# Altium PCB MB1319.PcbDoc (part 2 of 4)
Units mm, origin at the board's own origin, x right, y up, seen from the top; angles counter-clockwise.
Board outline 70 x 82.5 mm, 2 copper layers (Top Layer, Bottom Layer), stack 1.571 mm thick; 252 components, 179 nets, 814 pads, 1000 vias.
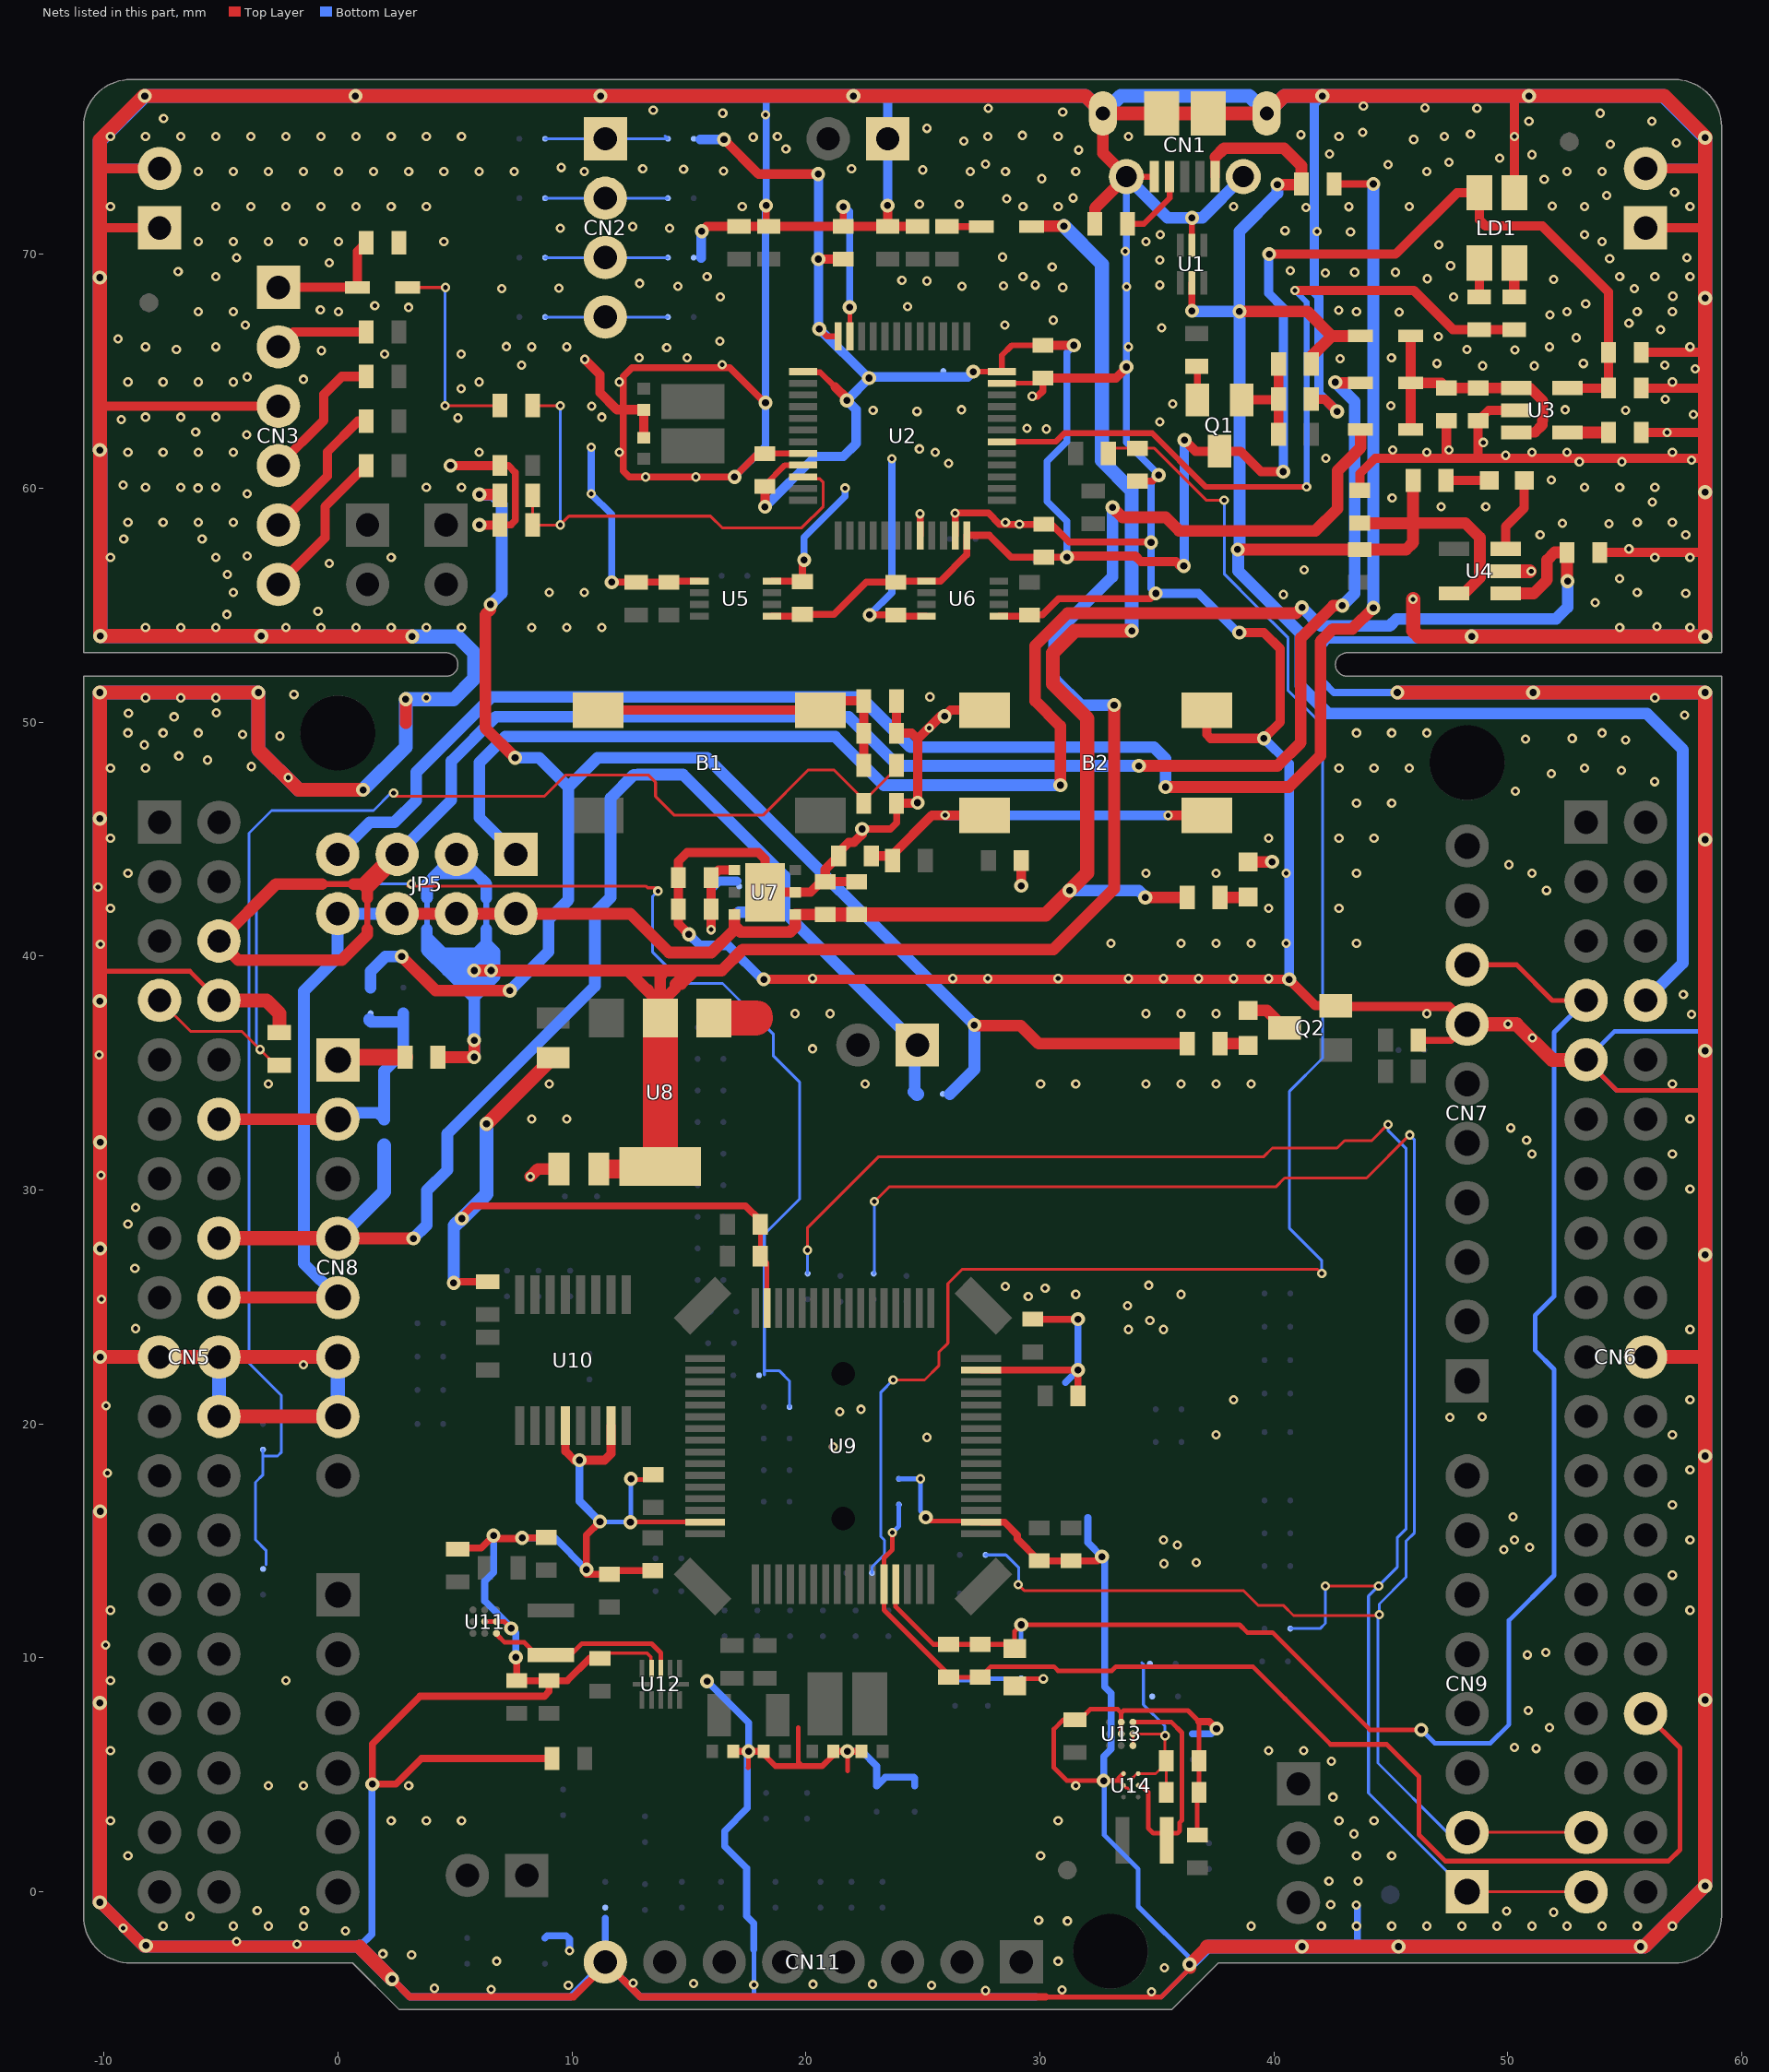
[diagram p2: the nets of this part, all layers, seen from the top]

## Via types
v1: diameter 0.4, hole 0.2, Top Layer to Bottom Layer, tented both sides, 802 vias
v2: diameter 0.6, hole 0.3, Top Layer to Bottom Layer, tented both sides, 198 vias

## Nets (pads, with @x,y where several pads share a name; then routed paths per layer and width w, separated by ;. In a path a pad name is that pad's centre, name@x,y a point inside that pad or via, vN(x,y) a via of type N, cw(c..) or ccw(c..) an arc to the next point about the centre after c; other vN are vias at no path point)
3V3: CN5.16 CN8.4 JP6.1 SB13.2 SB20.1 SB21.2 | length 61
  Top Layer w0.5: CN8.4@0,27.94 0.015,27.925 v2(3.225,27.925)
  Top Layer w0.6: CN5.16@-5.08,27.94 CN8.4@0,27.94
  Bottom Layer w0.5: v2(3.225,27.925) 3.8,28.5 3.8,29.975 4.675,30.85 4.675,32.4 10.981,38.706 10.981,41.834 11.65,42.503 ; 11.65,44.775 11.65,42.503 ; SB13.2@17.15,41.875 19.085,41.875 ; 24.65,34.2 JP6.1@24.65,36.08 ; JP6.1@24.765,36.195 19.085,41.875 ; 11.65,42.503 11.65,46.75 12.65,47.75 12.829,47.75 12.831,47.752 14.748,47.752 19.085,43.415 19.085,41.875
  Bottom Layer w0.6: CN8.4@0,27.94 1.975,29.915 SB21.2@1.975,31.9 ; 24.65,34.2 SB20.1@24.75,34.1 ; JP6.1@24.65,36.08 JP6.1@24.765,36.195
3V3_PER: R22.1 R34.1 SB15.2 SB20.2 | length 70.7
  Top Layer w0.5: v2(2.725,39.975) 4.175,38.525 v2(7.35,38.525) ; v2(6.05,59.725) 6.885,59.725 R22.1@6.92,59.69 ; v2(6.525,55.025) 6.525,54.81 6.3,54.585 6.3,49.75 v2(7.575,48.475) ; v2(27.2,37.05) 27.225,37.025 29.175,37.025 29.95,36.25 R34.1@36.3,36.25
  Bottom Layer w0.5: SB15.2@1.4,38.65 1.4,39.35 2.025,39.975 v2(2.725,39.975) ; v2(6.05,59.725) 6.025,59.7 6.625,59.7 7,59.325 7,55.5 v2(6.525,55.025) ; v2(7.35,38.525) 9,40.175 9,41.55 9.85,42.4 ; v2(7.575,48.475) 8.6,48.475 9.85,47.225 ; 9.85,43.925 9.85,42.4 ; 26.15,34.1 27.2,35.15 v2(27.2,37.05) 15.775,48.475 11.1,48.475 9.85,47.225 ; 9.85,42.4 9.85,47.225
3V3_ST_LINK: C1.2 C2.2 C3.2 C4.2 C11.2 C14.2 C16.2 C18.2 LD1.4 Q1.3 SB1.2 SB9.1 U2.1 U2.9 U2.24 U2.36 U2.48 U3.5 U5.1 U6.1 | length 114.3
  Top Layer w0.25: C11.2@18.25,60.075 18.25,60.125 19.105,60.98 U2.9@19.88,60.98 ; U2.1@19.88,64.98 19.905,64.955 20.615,64.955 21.245,64.325 ; v2(20.575,66.8) 20.895,66.48 U2.48@21.38,66.48 ; v2(27.15,64.975) 28.375,64.975 U2.36@28.38,64.98 28.38,65.68 28.8,66.1 C2.2@30.125,66.1
  Top Layer w0.3: U5.1@18.55,54.525 19.775,54.525 C16.2@19.85,54.6 21.2,54.6 22.575,55.975 C18.2@23.85,55.975 23.9,56.025 U6.1@25.15,56.025 25.75,56.025 26.88,57.155 U2.24@26.88,57.98 27.845,57.98 28.775,57.05 C14.2@30.175,57.05 v2(31.15,57.05)
  Top Layer w0.4: v2(16.5,74.9) 17.975,73.425 v2(20.525,73.425) ; v2(18.25,59.2) C11.2@18.25,60.075 ; v2(20.535,69.785) C1.2@21.59,69.785 ; 21.245,64.325 21.75,63.82 v2(21.75,63.75) ; C2.2@30.125,66.1 v2(31.45,66.1) ; v2(31.15,57.05) 31.2,57.1 34.075,57.1 34.315,56.86 35.816,56.86 36.001,56.675 v2(36.15,56.675) ; v2(36.175,62.05) 36.65,61.575 Q1.3@37.675,61.575 38.575,61.575 39.45,60.7 v2(40.4,60.7) ; v2(39.8,70) 45.2,70 47.82,72.62 LD1.4@48.78,72.62 48.78,71.47 49.05,71.2 51.475,71.2 54.3,68.375 C3.2@54.3,65.8 C4.2@54.3,64.275 U3.5@52.55,64.275
  Bottom Layer w0.3: v2(31.15,57.05) 31.15,58.575 30.3,59.425 30.3,61.15 31.15,62 31.15,65.8 v2(31.45,66.1)
  Bottom Layer w0.4: 15.475,74.9 v2(16.5,74.9) ; v2(18.25,59.2) 20.4,61.35 21.6,61.35 22.15,61.9 22.15,63.35 v2(21.75,63.75) v2(22.7,64.7) ; v2(20.525,73.425) 20.535,73.415 v2(20.535,69.785) 20.535,66.84 v2(20.575,66.8) 22.675,64.7 v2(22.7,64.7) ; v2(27.15,64.975) 26.925,64.75 22.75,64.75 v2(22.7,64.7) ; v2(36.15,56.675) 36.175,56.7 v2(36.175,62.05) ; v2(39.8,70) 39.775,69.975 39.775,68.325 40.4,67.7 v2(40.4,60.7)
5V: C25.2 C26.2 CN5.18 CN8.5 D1.1 JP5.2 JP5.4 JP5.6 JP5.8 R29.2 U7.1 U7.6 | length 97.1
  Top Layer w0.5: JP5.6@2.53,41.805 JP5.4@5.07,41.805 JP5.2@7.61,41.805 JP5.2@8.08,41.805 ; JP5.2@8.08,41.52 JP5.2@8.08,41.805 ; U7.6@16.95,41.775 16.95,41.289 ; C25.2@20.825,41.775 U7.1@19.55,41.775 19.55,41.25 19.325,41.025 17.214,41.025 16.95,41.289 ; D1.1@29.645,71.175 29.67,71.2 v2(31.025,71.2) ; v2(34.5,42.5) R29.2@36.3,42.5 R29.2@36.325,42.475 ; JP5.2@8.08,41.805 12.495,41.805 14.154,40.146 15.961,40.146 16.95,41.135 16.95,41.289
  Top Layer w0.508: CN5.18@-5.08,25.4 CN8.5@0,25.4
  Top Layer w0.6: C25.2@20.825,41.775 C26.2@22.175,41.775 30.25,41.775 v2(31.275,42.8) 32.025,43.55 32.025,50.15 30.55,51.625 30.55,52.957 31.493,53.9 v2(33.925,53.9)
  Bottom Layer w0.5: CN8.5@0,25.4 -1.45,26.85 -1.45,38.5 -0.01,39.94 JP5.8@-0.01,41.805 JP5.6@2.53,41.805 ; v2(31.275,42.8) 34.225,42.8 34.525,42.5 v2(34.5,42.5)
  Bottom Layer w0.6: v2(31.025,71.2) 32.65,69.575 32.65,61.175 33.925,59.9 v2(33.925,53.9)
5V_STLINK: C13.1 CN1.1 CN6.8 D3.1 R1.1 R13.1 R21.2 R25.1 U1.5 U4.5 | length 88.5
  Top Layer w0.3: v2(36.5,67.575) U1.5@36.5,68.77
  Top Layer w0.4: CN1.1@37.495,73.31 37.495,74.145 ; R1.1@41.15,72.975 R1.1@41.175,73
  Top Layer w0.5: 37.495,74.145 37.875,74.525 40.425,74.525 41.175,73.775 R1.1@41.175,73 ; v2(38.529,67.546) 41.421,67.546 41.425,67.55 42.475,66.5 ; v2(40.15,72.975) R1.1@41.15,72.975 ; 45.93,58.5 45.95,58.5 48.186,58.5 48.8,57.886 48.8,56.175 48.125,55.5 U4.5@47.7,55.5
  Top Layer w0.508: v2(38.45,57.375) R25.1@43.675,57.375 45.65,57.375 45.95,57.675 45.95,58.5 45.95,58.52 ; R13.1@41.6,65.3 41.6,65.625 42.475,66.5 D3.1@43.705,66.5 ; C13.1@43.675,58.5 45.93,58.5 45.95,58.52 ; R21.2@45.95,60.325 45.95,58.52
  Bottom Layer w0.25: v2(36.5,67.575) v2@36.525,67.55
  Bottom Layer w0.5: v2@36.525,67.55 36.529,67.546 v2(38.529,67.546) 38.529,70.679 38.529,70.979 40.15,72.6 v2(40.15,72.975)
  Bottom Layer w0.508: v2(38.529,67.546) 38.529,57.454 v2(38.45,57.375) 38.475,57.375 38.475,56.454 39.746,55.183 39.746,55.179 40.129,54.796 40.133,54.796 41.125,53.804 41.125,51.55 42.311,50.364 44.642,50.364 ; 45.075,50.364 44.642,50.364 ; CN6.8@55.88,38.1 57.475,39.695 57.475,48.825 55.936,50.364 44.642,50.364
5V_STLINK_SW: C15.2 JP5.1 U4.1 | length 68.2
  Top Layer w0.4: v2@41.15,54.9 v2(41.2,54.9)
  Top Layer w0.5: 30.875,48.025 v2(30.875,47.3) 30.875,49.825 29.8,50.9 29.8,53.268 31.182,54.65 40.95,54.65 v2(41.2,54.9) ; U4.1@49.9,55.5 51.1,55.5 51.675,56.075 51.675,56.925 52,57.25 C15.2@52.525,57.25 52.525,56.05 v2(52.55,56.025)
  Bottom Layer w0.5: JP5.1@7.61,44.345 6.05,45.905 6.05,48.275 7.15,49.375 21.25,49.375 23.325,47.3 v2(30.875,47.3) ; v2(41.2,54.9) 41.99,54.11 42.425,54.11 44.95,54.11 45.25,54.41 52.05,54.41 52.55,54.91 v2(52.55,56.025)
5V_USB_CHG: JP5.7 R1.2 | length 75.9
  Top Layer w0.3: R1.2@42.575,73 v2(44.25,73)
  Top Layer w0.5: v2(35.37,47.22) 40.645,47.22 41.99,48.565 41.99,53.438 42.527,53.975 43.35,53.975 v2(44.25,54.875)
  Bottom Layer w0.5: JP5.7@-0.01,44.345 1.355,45.71 1.95,45.71 1.96,45.72 2.42,45.72 3.35,46.65 3.35,47.862 6.563,51.075 22.325,51.075 24.475,48.925 34.875,48.925 35.37,48.43 v2(35.37,47.22) ; v2(44.25,54.875) v2(44.25,73)
5V_VIN: C29.2 D5.1 JP5.3 R35.2 U8.2 U8.4 | length 114.6
  Top Layer w0.5: R35.2@4.275,35.675 v2(5.825,35.675) v2(5.825,36.4) ; v2(5.825,39.377) 5.827,39.375 v2@5.843,39.375 ; v2@5.835,39.367 v2@5.843,39.375 ; v2(6.548,39.377) 5.845,39.377 v2@5.843,39.375 ; 13.25,38.55 13.2,38.55 ; U8.2@13.775,37.35 U8.2@13.775,37.975 ; 15.775,39.375 15.25,39.375 ; v2(33.102,59.175) 33.527,58.75 35.375,58.75 35.95,58.175 41.775,58.175 42.725,59.125 42.725,60.75 43.705,61.73 D5.1@43.705,62.5 ; 33.175,42.875 30.575,40.275 17.3,40.275 16.4,39.375 15.25,39.375 ; 33.175,42.95 v2(33.175,50.725) ; v2@5.843,39.375 12.375,39.375 ; 12.375,39.375 13.2,38.55 ; 12.375,39.375 13.775,39.375 ; 13.2,38.55 U8.2@13.775,37.975 ; U8.2@13.775,37.975 13.775,39.15 ; U8.2@13.775,37.975 14.425,38.625 14.425,38.8 ; 13.775,39.15 14,39.375 ; 13.775,39.15 13.775,39.375 ; 13.775,39.375 14,39.375 ; 14,39.375 15,39.375 ; 14.425,38.8 15,39.375 ; 14.425,38.8 14.675,38.8 15.25,39.375 ; 15,39.375 15.25,39.375
  Top Layer w0.8: C29.2@11.15,30.9 13.675,30.9 U8.4@13.775,31
  Top Layer w1.5: U8.4@13.775,31 U8.2@13.775,37.35
  Bottom Layer w0.25: 3.8,41.13 3.81,41.141 3.81,42.49 ; 6.34,41.13 6.34,42.48
  Bottom Layer w0.3: 30.675,51.8 30.675,53.775 ; v2@33,59.175 v2(33.102,59.175)
  Bottom Layer w0.5: 3.8,41.13 3.8,40.8 ; 3.81,42.49 3.81,43.085 4.25,43.525 ; v2(5.825,35.675) v2(5.825,36.4) 5.825,38.325 ; v2(5.825,39.377) 5.825,38.654 ; 6.34,41.13 6.34,40.525 ; 6.34,42.48 6.34,43.075 5.875,43.54 ; v2(33.102,59.175) 33.102,56.202 30.675,53.775 30.6,53.7 30.6,51.875 30.675,51.8 31.75,50.725 v2(33.175,50.725) ; 3.8,40.8 4.495,40.105 ; 3.8,40.8 3.8,40.25 4.673,39.377 ; 4.25,43.525 JP5.3@5.07,44.345 5.875,43.54 ; 4.25,43.525 5.86,43.525 5.875,43.54 ; 4.495,40.105 4.825,39.775 5.59,39.775 5.92,40.105 ; 4.495,40.105 5.92,40.105 ; 4.673,39.377 5.725,38.325 5.825,38.325 ; 4.673,39.377 5.102,39.377 ; 5.102,39.377 5.825,38.654 ; 5.102,39.377 v2(5.825,39.377) ; 5.825,38.325 5.825,38.654 ; 5.825,38.325 5.9,38.325 6.7,39.125 6.7,40.165 6.34,40.525 ; 5.825,38.654 v2(6.548,39.377) ; v2(5.825,39.377) 6.34,39.892 ; v2(5.825,39.377) v2(6.548,39.377) ; 5.92,40.105 6.34,40.525 ; 6.34,39.892 6.34,40.525 ; 6.34,39.892 6.34,39.585 v2(6.548,39.377)
AGND: C40.2 C41.1 CN6.32 SB56.2 U9.12 | length 52.3
  Top Layer w0.2: v1@23.773,15.279 v1(23.701,15.351) 23.701,14.63 23.34,14.269 U9.12@23.34,13.15 23.34,12.049 26.1,9.289 C41.1@26.1,9.175 ; C41.1@25.767,9.175 C41.1@26.1,9.175 ; CN6.32@55.88,7.62 57.35,6.15 57.35,1.8 56.865,1.315 47.325,1.315 46.2,2.44 46.2,4.925 44.825,6.3 42.425,6.3 40.475,8.25 39.1,9.625 33.25,9.625 33.075,9.45 30.775,9.45 30.6,9.625 27.9,9.625 C40.2@27.45,9.175 C41.1@26.1,9.175
  Bottom Layer w0.2: v1(23.701,15.351) 23.975,15.625 SB56.2@23.975,16.55
AIN_1: R16.2 R22.2 R24.2 U2.10 | length 22.7
  Top Layer w0.127: R22.2@8.32,59.69 R24.2@8.32,58.42 v1@9.5,58.42 ; R16.2@8.325,63.525 v1(9.5,63.525) ; v1(9.5,58.425) 9.876,58.801 15.924,58.801 16.423,58.302 19.824,58.302 20.744,59.221 20.744,60.239 20.589,60.393 19.967,60.393 U2.10@19.88,60.48
  Bottom Layer w0.127: v1(9.5,58.425) v1(9.5,63.525)
ARD_D0_RX: CN6.37 CN9.1 SB33.2 SB73.2 | length 74.7
  Top Layer w0.12: v1(20.075,27.425) 20.075,28.395 23.09,31.41 39.55,31.41 39.93,31.79 42.7,31.79 43.02,32.11 44.185,32.11 v1(44.875,32.8) ; v1(42.2,13.075) v1(44.475,13.075) v1@44.5,13.075 ; CN9.1@48.26,0 CN6.37@53.34,0
  Bottom Layer w0.12: SB33.2@20.075,26.425 v1(20.075,27.425) ; SB73.2@40.7,11.25 41.975,11.25 42.2,11.475 v1(42.2,13.075) ; v1(44.875,32.8) 44.875,32.55 45.64,31.785 45.64,15.502 45.27,15.132 45.27,13.87 v1(44.475,13.075) 44.042,12.642 44.042,4.218 CN9.1@48.26,0
ARD_D1_TX: CN6.35 CN9.2 SB35.2 SB60.2 | length 83.3
  Top Layer w0.12: v1(22.925,29.5) 23.555,30.13 40.08,30.13 40.46,30.51 43.96,30.51 v1(45.8,32.35) ; v1(29.076,13.126) 29.322,12.88 38.695,12.88 39.34,12.235 40.416,12.235 40.84,11.811 44.502,11.811 v1(44.502,11.851) ; CN9.2@48.26,2.54 CN6.35@53.34,2.54
  Bottom Layer w0.12: SB35.2@22.9,26.425 22.925,26.45 v1(22.925,29.5) ; SB60.2@27.675,14.4 28.55,14.4 29.1,13.85 29.1,13.149 v1(29.076,13.126) ; v1(44.502,11.851) 44.502,12.302 45.64,13.44 45.64,14.978 46.01,15.348 46.01,32.14 v1(45.8,32.35) ; v1@44.595,11.851 44.45,11.706 44.45,5.5 47.41,2.54 CN9.2@48.26,2.54
AVDD: C40.1 C41.2 CN6.7 CN7.8 L2.2 SB74.2 U9.13 | length 72.8
  Top Layer w0.2: U9.13@23.84,13.15 23.84,12.185 25.45,10.575 C41.2@26.1,10.575 C40.1@27.45,10.575 28.75,10.575 L2.2@28.925,10.4 28.925,11.138 v2(29.202,11.415) 38.534,11.415 38.864,11.085 ; 39.35,11.085 38.864,11.085 ; v2@46.35,6.925 44.1,6.925 39.94,11.085 38.864,11.085 ; CN7.8@48.26,39.624 50.376,39.624 51.9,38.1 CN6.7@53.34,38.1
  Bottom Layer w0.2: v2@29.142,11.475 v2(29.202,11.415) 29.2,11.413 SB74.2@29.2,10.225 ; v2(46.3,6.925) 46.875,6.35 49.25,6.35 50.05,7.15 50.05,11.6 51.975,13.525 51.975,22.334 51.16,23.149 51.16,24.636 51.975,25.451 ; 51.975,26.525 51.975,25.451 ; CN6.7@53.34,38.1 51.975,36.735 51.975,25.451
B_USER: C21.2 R30.1 SB50.1 SB62.1 | length 65.4
  Top Layer w0.12: v1(2.381,46.964) 2.364,46.964 2.275,46.875 2.326,46.824 8.826,46.824 9.742,47.74 13.261,47.74 13.575,47.426 13.575,46.822 14.382,46.015 18.165,46.015 20.109,47.959 21.191,47.959 22.475,46.675 C21.2@22.475,46.625 ; C21.2@22.475,46.525 C21.2@22.475,46.625 ; R30.1@23.875,48.15 23.875,48.025 C21.2@22.475,46.625
  Bottom Layer w0.12: SB50.1@-3.2,18.9 -3.2,18.625 ; -3.075,13.975 -3.075,14.6 -3.525,15.05 -3.525,17.5 -3.2,17.825 -3.2,18.625 ; v1(2.381,46.964) 2.264,46.964 1.52,46.22 -2.83,46.22 -3.8,45.25 -3.8,22.6 -2.41,21.21 -2.41,18.79 -2.575,18.625 -3.2,18.625
BOOT0: CN5.7 R32.2 SB45.2 SB48.2 | length 57.8
  Top Layer w0.12: CN5.7@-7.62,38.1 -6.295,36.775 -4.1,36.775 v1(-3.325,36) -2.65,35.325 R32.2@-2.5,35.325 ; v1(3.134,43.075) 3.07,43.075 2.985,42.99 13.159,42.99 13.234,42.915 13.535,42.915 v1(13.675,42.775)
  Bottom Layer w0.12: v1(-3.325,36) -3.48,36.155 -3.48,42.195 -2.6,43.075 v1(3.134,43.075) ; v1(13.675,42.775) 13.454,42.554 13.454,40.161 14.785,38.83 16.445,38.83 18.605,36.67 18.605,35.736 19.725,34.616 19.725,31.227 19.725,29.603 18.225,28.103 18.225,23.175
  Bottom Layer w0.127: 18.225,22.1 18.225,22.275 ; 18.225,23.175 18.225,22.275 ; SB48.2@19.3,20.725 19.3,21.825 18.85,22.275 18.225,22.275
E5V: CN5.6 D4.1 JP5.5 | length 80.2
  Top Layer w0.25: -0.685,43.075 0.665,43.075 ; 1.26,41.13 1.26,42.48
  Top Layer w0.4: 42.512,54.95 42.925,54.95 v2(42.925,54.975)
  Top Layer w0.5: -0.685,43.075 -2.645,43.075 CN5.6@-5.08,40.64 -4.265,39.825 0.175,39.825 1.26,40.91 1.26,41.13 ; 0.665,43.075 1.26,43.075 1.26,42.48 ; v2(34.225,48.125) 38.175,48.125 40.15,48.125 41.15,49.125 41.15,53.588 42.512,54.95 42.537,54.975 v2(42.925,54.975) ; v2(42.625,64.525) 42.65,64.5 D4.1@43.705,64.5
  Top Layer w0.8: 1.26,43.075 JP5.5@2.53,44.345
  Bottom Layer w0.5: JP5.5@2.53,44.345 4.85,46.665 4.85,48.325 6.75,50.225 21.825,50.225 23.925,48.125 v2(34.225,48.125) ; v2(42.625,64.525) 43.45,63.7 43.45,55.5 v2(42.925,54.975)
GND: B2.3 B2.4 C1.1 C2.1 C3.1 C4.1 C5.1 C6.1 C7.2 C8.1 C9.2 C10.2 C11.1 C12.1 C13.2 C14.1 C15.1 C16.1 C17.2 C18.1 C19.2 C20.1 C21.1 C22.1 C23.1 C24.1 C25.1 C26.1 C27.1 C28.1 C29.1 C30.2 C31.1 C32.1 C33.1 C34.1 C35.1 C36.1 C37.1 C38.1 C39.2 C42.1 C43.1 C44.1 C45.2 C46.2 C47.1 C48.1 C49.1 C50.1 C51.1 CN1.5 CN1.6 CN1.7 CN1.8 CN1.9 CN1.10 CN1.11 CN3.3 CN5.8 CN5.19 CN5.20 CN5.22 CN6.9 CN6.20 CN7.7 CN8.6 CN8.7 CN11.8 JP1.1 JP2.1 JP2.2 JP3.1 JP3.2 LD1.1 LD3.2 Q2.2 R2.1 R3.1 R4.1 R5.1 R6.2 R8.2 R15.1 R24.1 R26.2 R28.1 R32.1 R33.1 R37.1 R39.1 R43.2 R44.1 SB5.2 SB56.1 SB80.1 SB81.1 SB82.1 SB95.1 SB97.1 U1.2 U2.8 U2.20 U2.23 U2.35 U2.47 U3.2 U4.2 U5.4 U5.5 U6.4 U6.5 U7.2 U7.EP U8.1 U9.18 U9.31 U9.47 U9.63 U10.4 U10.7 U11.B1 U11.B2 U12.4 U13.B1 U13.B2 U14.A1 U14.C1 U14.D2 | length 1295
  Top Layer w0.12: 33.376,4.75 U14.C1@33.576,4.55 33.696,4.43 33.758,4.43 U14.D2@33.888,4.3
  Top Layer w0.15: C42.1@11.2,9.975 11.425,10.2 13.214,10.2 13.375,10.039 13.375,9.575 U12.4@13.4,9.55
  Top Layer w0.2: -10.17,6.1 -9.965,6.305 ; -10.17,39.4 -10.12,39.35 -6.33,39.35 CN5.8@-5.08,38.1 ; U11.B2@6.275,11.55 U11.B1@6.775,11.55 7.115,11.55 v2(7.405,11.26) ; v2(12.5,15.8) U9.63@15.69,15.8 ; v2(12.525,17.65) 12.525,17.775 12.375,17.625 13.275,17.625 C34.1@13.475,17.825 ; 17.525,5.3 17.55,5.325 v2(17.55,6) ; C30.2@18.05,28.75 18.05,28.7 C30.2@18.05,28.525 C31.1@18.05,27.175 18.34,26.885 U9.47@18.34,24.95 ; 19.675,7.025 19.675,5.55 19.825,5.4 ; 21.775,5.175 v2(21.775,6) ; U2.47@21.88,66.48 v2@21.88,67.72 ; v2(25.125,16) 25.275,15.85 27.49,15.85 U9.18@27.49,15.8 ; U2.35@28.38,64.48 29.905,64.48 C2.1@30.125,64.7 ; 30.25,-4.5 35.18,-4.5 v2@36.425,-3.255 ; v2(31.627,22.301) 31.628,22.3 v2(31.627,22.301) ; U13.B2@33.475,6.75 U13.B1@33.475,7.25 33.475,7.65 ; U14.A1@33.567,5.059 33.376,4.868 33.376,4.75 v2(32.725,4.75) 31.15,4.75 30.6,5.3 30.6,6.95 31,7.35 R43.2@31.5,7.35 31.7,7.35 32.15,7.8 33.325,7.8 33.475,7.65 ; C51.1@36.725,2.425 36.725,4.175 C50.1@36.8,4.25 C49.1@36.8,5.6 36.8,7.275 36.325,7.75 33.575,7.75 33.475,7.65 ; CN6.9@53.96,35.56 CN6.9@53.34,35.56 54.65,34.25 58.43,34.25 ; 58.405,36.825 58.43,36.85
  Top Layer w0.25: C46.2@18.2,5.87 18.695,5.375 20.7,5.375 C47.1@21.175,5.85 ; C11.1@18.25,61.475 18.255,61.48 U2.8@19.88,61.48 ; CN1.7@33.695,73.31 CN1.5@34.895,73.31 ; U1.2@36.5,70.38 v2(36.5,71.55)
  Top Layer w0.3: v2(2.315,-3.735) 3.07,-4.49 10.075,-4.49 11.43,-3.135 CN11.8@11.43,-3 12.92,-4.49 30.25,-4.49 ; v2(4.95,26.025) 5,26.075 R37.1@6.4,26.075 ; R39.1@5.125,14.65 5.125,14.7 6.125,14.7 v2(6.65,15.226) 6.674,15.226 6.8,15.1 7.85,15.1 v2(7.875,15.125) 8.875,15.125 C37.1@8.9,15.15 ; v2(5.3,28.775) 5.25,28.825 5.75,29.325 17.425,29.325 C30.2@18.05,28.7 ; R24.1@6.92,58.42 7.395,58.42 7.59,58.615 7.59,60.66 7.29,60.96 C12.1@6.92,60.96 ; v2(7.6,10.025) 7.6,10.016 7.65,10.066 v2@7.65,9.854 ; C43.1@7.65,9.025 C44.1@9.025,9.025 ; C43.1@7.65,9.1 v2@7.65,9.854 ; R44.1@9.15,5.7 3.575,5.7 2.475,4.6 v2(1.475,4.6) 1.475,6.325 3.508,8.358 8.818,8.358 9.025,8.564 C44.1@9.025,9.025 ; 10.75,9.975 9.8,9.025 C44.1@9.025,9.025 ; v2(11.2,15.825) 10.625,15.25 v2(10.625,13.775) 10.625,13.575 C39.2@11.6,13.575 11.75,13.725 C38.1@13.45,13.725 ; v2(11.7,55.975) R26.2@12.75,55.975 C17.2@14.15,55.975 14.2,56.025 U5.5@15.45,56.025 ; 12.25,63.35 12.2,63.3 ; C45.2@16.9,6 v2(17.55,6) C46.2@18.2,6 C46.2@18.2,5.87 ; C11.1@18.25,61.475 17.95,61.475 v2(16.95,60.475) 12.45,60.475 12.2,60.725 12.2,63.3 ; v2(18.275,63.65) 18.25,63.65 16.75,65.15 12.575,65.15 12.2,64.775 12.2,63.35 12.2,63.3 ; v2(18.3,72.075) 18.3,71.3 R4.1@18.415,71.185 ; U5.4@18.55,56.025 19.825,56.025 C16.1@19.85,56 19.85,56.85 v2(19.925,56.925) ; C47.1@21.175,5.85 C47.1@21.175,6 v2(21.775,6) C48.1@22.375,6 ; C1.1@21.59,71.185 21.6,71.195 v2(21.6,72.025) ; v2(21.875,67.725) v2@21.88,67.72 ; v2(22.401,45.427) 23.602,45.427 23.875,45.7 C21.1@23.875,46.525 ; v2(22.725,54.575) C18.1@23.85,54.575 23.9,54.525 U6.4@25.15,54.525 ; U2.20@24.88,57.98 v1(24.88,58.9) ; U2.23@26.38,57.98 v1(26.38,58.925) 26.385,58.93 27.795,58.93 28.275,58.45 C14.1@30.175,58.45 30.5,58.45 31.25,57.7 34.725,57.7 v2(34.75,57.675) ; U9.18@27.49,15.8 28.485,15.8 29.035,15.25 29.035,15.09 C35.1@29.975,14.15 C36.1@31.325,14.15 32.475,14.15 v2(32.65,14.325) ; U9.31@27.49,22.3 v2(31.627,22.301) v2(31.627,22.301) ; U6.5@28.25,54.525 29.5,54.525 C19.2@29.55,54.575 30.1,54.575 30.8,55.275 34.725,55.275 v2(34.95,55.5) ; v1(29.675,63.925) 29.9,63.925 30.125,64.15 C2.1@30.125,64.7 ; C32.1@29.7,24.475 v2(31.625,24.475) ; C33.1@31.625,21.2 v2(31.627,22.301) ; C10.2@34.175,60.3 34.825,60.3 v2(35.075,60.55) ; 36.8,7.275 37.25,7.275 v2(37.55,6.975) ; R33.1@46.175,36.4 47.576,36.4 CN7.7@48.26,37.084
  Top Layer w0.35: CN8.6@0,22.86 CN8.6@0.285,22.86 ; U10.4@9.725,19.925 9.725,18.825 10.1,18.45 v2(10.325,18.45)
  Top Layer w0.4: -10.17,63.5 CN3.3@-2.54,63.5 ; -10.17,70.975 -10.025,71.12 JP2.1@-7.62,71.12 ; -10.17,73.75 -10.08,73.66 JP2.2@-7.62,73.66 ; 2.605,76.665 2.7,76.76 ; v2(4.815,60.96) C12.1@6.92,60.96 ; v2(6.05,58.428) 6.045,58.423 6.045,58.42 R24.1@6.92,58.42 ; v2(10.325,18.45) 11.399,18.45 11.675,18.726 U10.7@11.675,19.925 ; v1(10.55,65.5) 11.2,64.85 11.2,64.075 11.925,63.35 12.2,63.35 12.25,63.35 C7.2@13.075,63.35 C9.2@13.075,62.15 ; v2(15,40.925) 14.55,41.375 C27.1@14.55,42 C24.1@14.55,43.35 14.55,44.05 14.925,44.425 17.975,44.425 18.25,44.15 U7.EP@18.25,42.725 U7.2@19.55,42.725 20.2,42.725 20.65,43.175 C25.1@20.825,43.175 ; v2(15.55,70.975) 15.76,71.185 R3.1@17.145,71.185 R4.1@18.415,71.185 C1.1@21.59,71.185 R5.1@23.495,71.185 ; v2(18.2,39) v2(40.65,39) 41.775,37.875 Q2.2@42.65,37.875 42.65,37.84 47.504,37.84 CN7.7@48.26,37.084 ; C26.1@22.2,43.2 C26.1@22.175,43.175 C25.1@20.825,43.175 ; v2(22.401,45.427) 22.401,45.201 22.32,45.12 22.314,45.12 22.08,44.886 22.08,44.88 22.05,44.85 21.824,44.85 21.4,44.426 C22.1@21.4,44.275 20.825,43.7 C25.1@20.825,43.175 ; v2(23.49,72.075) 23.495,72.07 R5.1@23.495,71.185 ; C21.1@23.875,46.525 24.775,46.525 v2(24.775,46.55) 24.775,49.275 ; R28.1@23.875,50.9 C20.1@23.875,49.525 24.525,49.525 24.775,49.275 ; R6.2@24.765,71.185 R5.1@23.495,71.185 ; B2.4@27.635,50.51 26.185,50.51 v2(25.925,50.25) 25.75,50.25 24.775,49.275 ; v2(29.2,43) C23.1@29.2,44.075 ; C2.1@30.125,64.7 33.25,64.7 33.725,65.175 v2(33.7,65.175) ; B2.3@37.135,50.51 37.135,49.465 37.3,49.3 v2(39.575,49.3) 40.275,50 40.275,53.125 39.575,53.825 v2(38.525,53.825) ; R15.1@41.6,63.8 42.175,63.8 v2(42.7,63.275) ; C13.2@43.675,59.9 43.675,60.625 44.325,61.275 47.35,61.275 ; C5.1@47.375,62.875 47.375,61.3 47.35,61.275 ; 50.15,76.76 50.28,76.63 LD1.1@50.28,72.62 ; U3.2@50.35,63.325 49.175,63.325 C6.1@48.725,62.875 48.725,61.3 48.75,61.275 ; C15.1@53.925,57.25 58.43,57.25 ; C8.1@55.7,62.375 58.405,62.375 58.43,62.4 ; C4.1@55.7,64.275 58.43,64.275 ; C3.1@55.7,65.8 58.405,65.8 58.43,65.825 ; JP3.1@55.88,71.12 58.375,71.12 58.43,71.175 ; JP3.2@55.88,73.66 58.42,73.66 58.43,73.65 ; 58.43,61.275 48.75,61.275 ; 47.35,61.275 48.75,61.275
  Top Layer w0.5: v2(-10.17,-0.45) v2@-8.28,-2.34 ; v2@-8.2,-2.34 0.92,-2.34 ; 2.9,49.95 v2(2.9,50.975) ; v2(6.35,32.825) v2@6.375,32.825 ; v1(8.225,30.575) 8.55,30.9 C29.1@9.45,30.9 ; R2.1@32.35,71.3 32.35,71.965 CN1.7@33.695,73.31 32.695,74.31 CN1.8@32.695,76.01 ; v2@36.425,-3.255 36.425,-3.05 37.135,-2.34 ; LD3.2@38.9,44.025 v2(39.925,44.025)
  Top Layer w0.6: v2(-10.17,-0.45) -10.17,6.1 v2(-10.17,8.075) -10.17,16.25 v2(-10.16,16.26) v2(-10.16,22.86) ; CN5.22@-5.08,20.32 CN8.7@0,20.32 ; CN5.8@-5.08,38.1 -3.05,38.1 -2.5,37.55 R32.1@-2.5,36.725 ; CN8.6@0,22.86 CN5.20@-5.08,22.86 CN5.19@-7.62,22.86 v2(-10.16,22.86) ; 0.92,-2.34 v2(2.315,-3.735) ; v2(1.075,47.1) -1.675,47.1 -3.4,48.825 v2(-3.4,51.26) v2(-10.17,51.26) v2(-10.17,45.875) -10.17,39.4 v2(-10.17,38.075) -10.17,32.05 v2(-10.16,32.04) v2(-10.16,27.49) v2(-10.16,22.86) ; v2(3.175,53.66) -3.26,53.66 v2(-3.275,53.675) v2(-10.155,53.675) -10.155,61.61 v2(-10.17,61.625) -10.17,63.5 v2(-10.17,69) -10.17,70.975 -10.17,73.75 -10.17,74.89 -8.3,76.76 v2(-8.25,76.76) v2(0.75,76.76) 2.7,76.76 v2(11.225,76.76) v2(22.025,76.76) 31.945,76.76 CN1.8@32.695,76.01 CN1.11@35.195,76.01 CN1.10@37.195,76.01 CN1.9@39.695,76.01 40.445,76.76 v2(42.075,76.76) 50.15,76.76 v2(50.9,76.76) 56.695,76.76 58.43,75.025 v2(58.43,74.975) 58.43,73.65 58.43,71.175 v2(58.43,68.125) 58.43,65.825 58.43,64.275 58.43,62.4 58.43,61.275 v2(58.43,59.825) 58.43,57.25 v2(58.43,53.66) v2(48.45,53.66) 46.19,53.66 45.95,53.9 v1(45.95,55.25) ; v2@6.375,32.825 C28.1@9.2,35.65 ; 37.135,-2.34 v2(41.2,-2.34) v2(45.325,-2.34) v2(55.675,-2.34) 55.84,-2.34 v2(58.43,0.25) v2(58.43,8.2) v2(58.43,18.625) 58.43,22.8 ; v2(45.275,51.26) v2(51.075,51.26) v2(58.43,51.26) v2(58.43,44.975) 58.43,36.85 v2(58.43,35.95) 58.43,34.25 v2(58.43,27.225) 58.43,22.8 ; CN7.7@48.26,37.084 v1(50,37.084) 50.366,37.084 51.89,35.56 CN6.9@53.34,35.56 ; U4.2@49.9,56.45 v1@50.925,56.45 ; CN6.20@55.88,22.86 58.37,22.86 58.43,22.8
  Top Layer w1: U8.1@16.075,37.35 U8.1@16.225,37.35
  Top Layer w1.2: 17.85,37.35 17.975,37.475
  Top Layer w1.5: U8.1@16.225,37.35 17.85,37.35
  Bottom Layer w0.2: -10.17,3.8 -10.145,3.775 ; v2(11.2,15.825) 11.225,15.8 v2(12.5,15.8) 12.525,15.825 v2(12.525,17.65) ; 17.78,-2.467 17.78,-4.47 17.8,-4.49 ; SB56.1@23.975,17.65 v1(24.9,17.65) 24.9,16.275 25.125,16.05 v2(25.125,16) ; 29.825,-4.49 35.19,-4.49 v2@36.49,-3.19 ; v2(31.625,24.475) v2(31.625,24.475) ; v2(32.725,4.75) 32.749,4.75 32.749,2.426 34.2,0.975 34.2,-0.625 v2@36.562,-2.987 ; 58.43,34.3 58.38,34.25 54.65,34.25 CN6.9@53.34,35.56 54.565,36.785 58.42,36.785 58.43,36.775
  Bottom Layer w0.3: 0.92,-2.34 1.45,-1.81 v2@1.45,4.6 ; v2@1.323,4.6 v2@1.45,4.6 ; v2(2.315,-3.735) 3.07,-4.49 9.94,-4.49 CN11.8@11.43,-3 ; v2(6.65,15.226) 6.65,13.645 6.275,13.27 6.275,12.431 7.405,11.301 v2(7.405,11.26) 7.6,11.065 v2@7.6,10.107 ; v2@7.591,10.116 v2@7.6,10.107 ; v2(7.6,10.025) v2@7.6,10.107 ; v2(7.875,15.125) 9.275,15.125 v2(10.625,13.775) ; SB97.1@8.85,-1.975 8.95,-1.875 9.75,-1.875 9.9,-2.025 v1(9.9,-2.525) ; v1(10.825,61.75) v1(10.825,59.75) 11.7,58.875 v2(11.7,55.975) ; 11.425,-1.125 11.425,-2.995 CN11.8@11.43,-3 ; v2(15.775,8.995) 15.775,9 17.55,7.225 v2(17.55,6) 17.5,5.95 17.5,3.575 16.525,2.6 16.525,1.95 17.465,1.01 17.465,-1.031 17.78,-1.346 17.78,-2.467 ; v2(16.95,60.475) 18.275,61.8 v2(18.275,63.65) 18.275,72.075 v2(18.3,72.075) 18.3,76.71 18.25,76.76 ; v2(19.925,56.925) 19.925,57.9 21.675,59.65 v1(21.675,60) ; v2(21.6,72.025) 21.6,72.1 21.875,71.825 v2(21.875,67.725) ; v2(21.775,6) 22.4,6 23.025,5.375 SB81.1@23.025,4.525 23.4,4.9 24.6,4.9 24.65,4.85 SB82.1@24.65,4.525 ; v2(22.725,54.575) 23.675,55.525 v1(23.675,61.25) ; 29.825,-4.49 17.8,-4.49 12.92,-4.49 CN11.8@11.43,-3 ; 31.1,21.775 v2(31.627,22.301) v2(31.625,24.475) ; 32.05,16 32.05,14.925 v2(32.65,14.325) 32.775,14.2 32.775,8.756 33.052,8.479 33.052,6.105 32.725,5.778 v2(32.725,4.75) ; CN1.7@33.695,73.31 33.695,61.955 v2@35.075,60.575 ; v2(34.95,55.5) 34.75,55.7 v2(34.75,57.675) 34.75,60.25 v2@35.075,60.575 ; v2(35.075,60.55) v2@35.075,60.575 ; SB80.1@36.525,6.75 37.325,6.75 v2(37.55,6.975) ; v1(43.525,-0.575) 43.575,-0.625 43.575,-2.34 ; v2(45.275,51.26) 42.565,51.26 42.09,51.735 42.09,53.265 42.335,53.51 48.3,53.51 v2(48.45,53.66) ; v2@1.45,4.6 v2(1.475,4.6) 1.45,4.625 v2@1.45,4.6
  Bottom Layer w0.35: v2(10.325,18.45) 10.325,16.7 v2(11.2,15.825)
  Bottom Layer w0.4: -10.17,71.075 -10.125,71.12 JP2.1@-7.62,71.12 ; -10.17,73.675 -10.155,73.66 JP2.2@-7.62,73.66 ; 4.775,53.66 4.815,53.7 ; v2@6.022,58.428 v2(6.05,58.428) ; v2(15,40.925) 15.475,40.45 16.675,40.45 18.2,38.925 v2(18.2,39) ; 15.525,69.825 15.525,70.975 v2(15.55,70.975) ; v2(22.401,45.427) v2@22.403,45.425 ; v2(23.49,72.075) 23.495,72.08 JP1.1@23.495,74.93 23.495,76.68 23.575,76.76 ; v2(34.95,55.5) 36.781,55.5 38.456,53.825 v2(38.525,53.825) ; v2(39.575,49.3) 40.65,48.225 v2(40.65,39) ; v2(42.075,76.76) 41.725,76.41 41.725,68.367 41.925,68.167 41.925,64.05 v2(42.7,63.275) ; JP3.1@55.88,71.12 58.41,71.12 58.43,71.1 ; JP3.2@55.88,73.66 58.395,73.66 58.43,73.625
  Bottom Layer w0.5: v2(-10.17,-0.45) v2@-8.28,-2.34 ; v2@-8.2,-2.34 0.92,-2.34 ; v2(4.95,26.025) 4.95,28.375 5.025,28.45 5,28.475 ; CN1.7@33.695,73.31 35.455,71.55 v2(36.5,71.55) 36.935,71.55 CN1.6@38.695,73.31 ; v2@36.562,-2.987 37.21,-2.34
  Bottom Layer w0.6: v2(-10.17,-0.45) -10.17,3.8 v2(-10.17,8.075) -10.17,16.25 v2(-10.16,16.26) v2(-10.16,22.86) v2(-10.16,27.49) v2(-10.16,32.04) -10.16,38.065 v2(-10.17,38.075) v2(-10.17,45.875) v2(-10.17,51.26) v2(-3.4,51.26) -3.4,48.825 -1.675,47.1 v2(1.075,47.1) 2.9,48.925 v2(2.9,50.975) 4.945,50.975 5.82,51.85 5.82,52.953 5.113,53.66 4.775,53.66 v2(3.175,53.66) -3.26,53.66 v2(-3.275,53.675) v2(-10.155,53.675) -10.155,61.61 v2(-10.17,61.625) v2(-10.17,69) -10.17,71.075 -10.17,73.675 -10.17,74.84 v2(-8.25,76.76) v2(0.75,76.76) v2(11.225,76.76) 18.25,76.76 v2(22.025,76.76) 23.575,76.76 31.945,76.76 CN1.8@32.695,76.01 33.445,76.76 38.945,76.76 CN1.9@39.695,76.01 40.445,76.76 v2(42.075,76.76) v2(50.9,76.76) 56.645,76.76 v2(58.43,74.975) 58.43,73.625 58.43,71.1 v2(58.43,68.125) v2(58.43,59.825) v2(58.43,53.66) v2(48.45,53.66) ; CN5.22@-5.08,20.32 CN5.20@-5.08,22.86 ; CN8.7@0,20.32 CN8.6@0,22.86 ; 0.92,-2.34 v2(2.315,-3.735) ; 5,28.475 v2(5.3,28.775) 6.35,29.825 v2(6.35,32.825) ; 37.21,-2.34 v2(41.2,-2.34) 43.575,-2.34 v2(45.325,-2.34) v2(55.675,-2.34) 55.84,-2.34 v2(58.43,0.25) v2(58.43,8.2) v2(58.43,18.625) v2(58.43,27.225) 58.43,34.3 v2(58.43,35.95) 58.43,36.775 v2(58.43,44.975) v2(58.43,51.26) v2(51.075,51.26) v2(45.275,51.26)
  other v1: 34.775,-4.275 27.675,-4.225 30.95,-4.2 6.55,-4.175 4.125,-4.125 9.85,-4 25.375,-4 17.775,-3.975 20.3,-3.95 22.85,-3.95 15.2,-3.925 12.625,-3.9 35.325,-3.25 6.78,-2.965 30.78,-2.965 3.15,-2.7 1.925,-2.65 -1.75,-2.25 -4.325,-2.125 0.325,-1.675 -9.175,-1.55 -7.47,-1.465 -4.47,-1.465 -2.97,-1.465 -1.47,-1.465 39.03,-1.465 42.03,-1.465 43.53,-1.465 45.03,-1.465 46.53,-1.465 48.03,-1.465 49.53,-1.465 51.03,-1.465 52.53,-1.465 54.03,-1.465 55.53,-1.465 57.03,-1.465 31.175,-1.25 29.95,-1.225 -6.325,-1.05 51.95,-0.875 49.95,-0.825 -3.45,-0.8 -1.425,-0.8 42.425,-0.55 42.35,0.45 43.6,0.45 -8.97,1.535 30.03,1.535 43.53,1.535 45.03,1.535 43.425,2.475 -9.72,3.035 2.28,3.035 3.78,3.035 5.28,3.035 30.78,3.035 42.78,3.035 44.28,3.035 42.525,4.05 -2.97,4.535 -1.47,4.535 3.03,4.535 31.53,4.535 42.45,5.575 -9.72,6.035 39.78,6.035 41.28,6.035 51.2,6.125 50.275,6.175 51.775,7.025 50.875,7.75 -9.72,9.035 -2.22,9.035 50.825,10.125 51.625,10.225 -9.925,10.55 -9.72,12.035 57.78,12.035 57.03,13.535 35.3,14.025 36.675,14.075 49.825,14.625 50.925,14.725 35.875,14.825 35.28,15.035 50.28,15.035 57.78,15.035 50.225,16.025 57.03,16.535 -9.85,17.9 57.78,18.035 21.175,19.025 25.175,19.425 37.53,19.535 57.03,19.535 47.525,20.275 48.9,20.3 21.45,20.525 22.35,20.625 -9.9,20.775 38.28,21.035 57.78,21.035 -1.47,22.535 33.78,24.035 35.28,24.035 57.78,24.035 -8.65,24.075 34.7,24.425 33.75,25.05 -10.1,25.325 29.5,25.45 31.53,25.535 36.03,25.535 30.225,25.8 28.525,25.875 34.65,25.925 -8.675,26.65 -8.97,28.535 -8.65,29.25 57.78,30.035 -10.125,30.625 51.03,31.535 57.03,31.535 50.8,32.125 50.125,32.65 8.28,33.035 9.78,33.035 57.78,33.035 -2.97,34.535 9.03,34.535 22.53,34.535 30.03,34.535 31.53,34.535 34.53,34.535 36.03,34.535 37.53,34.535 39.03,34.535 57.03,34.535 -10.2,35.775 20.28,36.035 51.05,36.5 57.85,37.5 19.53,37.535 21.03,37.535 34.53,37.535 36.03,37.535 37.53,37.535 46.53,37.535 57.5,38.35 20.28,39.035 26.28,39.035 27.78,39.035 30.78,39.035 33.78,39.035 35.28,39.035 36.78,39.035 38.28,39.035 39.78,39.035 -10.15,40.5 33.03,40.535 36.03,40.535 37.53,40.535 39.03,40.535 40.53,40.535 43.53,40.535 -9.72,42.035 39.78,42.035 42.78,42.035 51.65,42.8 -10.25,42.95 -8.97,43.535 34.53,43.535 37.53,43.535 40.53,43.535 43.53,43.535 51.03,43.535 50.05,43.9 -9.72,45.035 39.78,45.035 42.78,45.035 44.28,45.035 43.53,46.535 45.03,46.535 50.325,47.05 56.275,47.45 -2.125,47.625 51.85,47.8 54.85,47.925 -9.72,48.035 -8.22,48.035 42.78,48.035 44.28,48.035 45.78,48.035 53.28,48.035 -3.7,48.1 -5.575,48.375 -6.8,48.55 -8.275,49.025 55.025,49.225 50.75,49.275 52.75,49.3 -2.475,49.4 -4.075,49.475 -8.97,49.535 -7.47,49.535 -5.97,49.535 43.53,49.535 45.03,49.535 46.53,49.535 54.03,49.535 25.275,49.75 -7,50.225 57.55,50.3 -8.95,50.375 -5.2,50.4 -8.22,51.035 -6.72,51.035 -5.22,51.035 3.78,51.035 56.28,51.035 25.3,51.075 -1.875,51.175 -8.22,54.035 -6.72,54.035 -5.22,54.035 -2.22,54.035 -0.72,54.035 0.78,54.035 2.28,54.035 3.78,54.035 5.28,54.035 8.28,54.035 9.78,54.035 11.28,54.035 54.78,54.035 57.78,54.035 56.375,54.075 -4.75,54.6 -0.85,54.725 53.725,55.1 40.4,55.45 57.6,55.5 -4.47,55.535 9.03,55.535 10.53,55.535 55.53,55.535 54.775,56.125 -4.725,56.3 51,56.45 41.3,56.5 -0.375,56.775 -9.72,57.035 -5.22,57.035 2.28,57.035 56.28,57.035 57.78,57.035 -3.875,57.1 55.175,57.4 -9.15,57.825 -5.8,57.825 51.375,58 57.6,58 29.125,58.45 54.325,58.475 52.325,58.5 -8.97,58.535 -7.47,58.535 -5.97,58.535 -4.47,58.535 28.53,58.535 55.53,58.535 57.03,58.535 47.15,59.2 49.05,59.2 56.175,59.4 45.05,59.575 -3.875,59.75 -5.975,60 -8.22,60.035 -6.72,60.035 -5.22,60.035 3.78,60.035 5.28,60.035 53.28,60.035 54.78,60.035 56.28,60.035 -9.175,60.125 51.85,60.35 13.15,60.475 15.3,60.475 26.1,61.05 53.05,61.125 54.875,61.125 57.85,61.2 42.225,61.275 49.9,61.4 -8.97,61.535 -7.47,61.535 -5.97,61.535 -4.47,61.535 6.03,61.535 12.03,61.535 25.53,61.535 46.53,61.535 51.03,61.535 52.53,61.535 57.03,61.535 45.075,61.625 47.475,61.625 24.85,61.675 48.95,61.95 -3.9,62.275 56.8,62.375 -6.075,62.4 30.275,62.525 29.45,62.55 35.125,62.825 -9.25,62.925 5.125,63 -8.22,63.035 -6.72,63.035 -5.22,63.035 11.28,63.035 57.925,63.15 24.75,63.275 22.875,63.325 55.025,63.325 26.65,63.35 52.45,63.35 10.85,63.5 45,63.525 35.675,63.6 56.725,63.8 5.275,64.25 -8.97,64.535 -7.47,64.535 -5.97,64.535 -4.47,64.535 6.03,64.535 12.03,64.535 57.03,64.535 -1.475,64.65 -3.875,64.75 58,65.1 48.925,65.225 51.125,65.225 7.85,65.25 56.7,65.25 16.425,65.275 46.975,65.325 53.225,65.325 42.825,65.525 12.875,65.575 14.925,65.575 45.025,65.575 2,65.725 5.275,65.725 -0.7,65.875 50.3,65.9 -6.9,65.925 48.25,65.925 14.05,66 -8.22,66.035 -5.22,66.035 7.2,66.05 8.28,66.035 9.78,66.035 33.78,66.035 51.78,66.035 57.78,66.035 16.325,66.275 -9.4,66.375 52.925,66.425 47.025,66.475 56.525,66.775 35.2,66.85 -3.95,66.975 28.5,66.975 55.175,67.05 30.575,67.175 51.8,67.4 45.35,67.525 -5.97,67.535 -4.47,67.535 0.03,67.535 43.53,67.535 52.53,67.535 55.53,67.535 57.03,67.535 42.775,67.6 -0.75,67.625 3.025,67.725 24.35,67.75 1.575,67.8 53.325,67.875 16.35,68.175 47.675,68.175 57.05,68.2 7,68.525 55.4,68.525 9.45,68.55 30.975,68.575 33.7,68.6 14.525,68.625 26.675,68.625 28.45,68.65 29.8,68.675 35.125,68.675 12.9,68.75 25.175,68.85 24.1,68.875 51.95,68.925 46.55,68.95 -5.22,69.035 15.78,69.035 29.28,69.035 54.78,69.035 56.28,69.035 57.78,69.035 42.2,69.2 43.45,69.225 45.2,69.225 -6.825,69.25 40.7,69.3 30.525,69.45 47.55,69.5 -0.375,69.625 35.125,69.75 54.35,69.8 -4.325,69.85 57.65,69.85 28.4,69.875 33.65,70.125 47.05,70.4 -5.97,70.535 -4.47,70.535 -2.97,70.535 -1.47,70.535 0.03,70.535 4.53,70.535 34.53,70.535 54.03,70.535 35.15,70.825 53.275,70.825 43.275,70.95 41.85,70.975 40.475,71 9.5,71.1 14.175,71.1 12.6,71.175 41.375,72 43.2,72.025 -9.72,72.035 -5.22,72.035 -3.72,72.035 -2.22,72.035 -0.72,72.035 0.78,72.035 2.28,72.035 3.78,72.035 17.28,72.035 29.28,72.035 30.78,72.035 38.28,72.035 45.78,72.035 51.9,72.05 53.28,72.035 57.78,72.035 24.85,72.125 26.55,72.125 28.575,72.375 31.425,72.4 54.225,72.5 57.125,72.65 51.55,73.2 30.075,73.225 -5.97,73.535 -4.47,73.535 -2.97,73.535 -1.47,73.535 0.03,73.535 1.53,73.535 3.03,73.535 4.53,73.535 6.03,73.535 7.53,73.535 10.53,73.535 27.03,73.535 28.53,73.535 31.53,73.535 46.53,73.535 52.53,73.535 54.03,73.535 16.475,73.55 25,73.6 14.775,73.625 13.025,73.65 21.95,73.65 9.55,73.7 44.875,73.825 27.675,73.85 47.475,73.925 49.65,74.1 51.025,74.25 42.375,74.275 31.65,74.45 19.15,74.5 54.375,74.7 57.2,74.75 26.75,74.825 45.975,74.9 17.75,75 -9.72,75.035 -8.22,75.035 -6.72,75.035 -5.22,75.035 -3.72,75.035 -2.22,75.035 -0.72,75.035 0.78,75.035 2.28,75.035 3.78,75.035 5.28,75.035 18.78,75.035 27.78,75.035 30.78,75.035 33.78,75.035 42.78,75.035 47.28,75.035 50.28,75.035 29.25,75.075 41.15,75.1 48.4,75.125 43.8,75.2 25.175,75.375 50.9,75.675 56.15,75.675 -7.45,75.8 18.275,75.95 16.45,76.025 53.95,76.025 30.975,76.075 13.475,76.15 27.8,76.225 48.675,76.225 46.45,76.25 43.825,76.325
  other v2: 36.4,-3.1 -8.2,-2.3
IOREF: CN5.12 CN8.2 SB14.1 SB15.1 SB21.1 | length 13.7
  Top Layer w0.5: CN5.12@-5.08,33.02 CN8.2@0,33.02
  Bottom Layer w0.5: CN8.2@0,33.02 0.28,33.3 1.725,33.3 SB21.1@1.975,33.05 ; 1.35,37.3 1.35,37.25 1.425,37.175 2.8,37.175 ; SB21.1@1.975,33 SB21.1@1.975,33.05 ; SB14.1@2.8,37.55 2.8,37.175 ; SB21.1@1.975,33.05 1.975,35.075 2.8,35.9 2.8,37.175
LED_STLINK: R9.2 R10.2 U2.30 | length 32.8
  Top Layer w0.25: U2.30@28.38,61.98 30.68,61.98 31.045,62.345 34.795,62.345 37.09,60.05 v1(41.4,60.05)
  Top Layer w0.4: v1(40.9,68.45) 45.975,68.45 47.65,66.775 R9.2@48.775,66.775 R10.2@50.275,66.775
  Bottom Layer w0.25: v1(40.9,68.45) 41.4,67.95 v1(41.4,60.05)
MCO: C10.1 R19.2 SB64.1 | length 72.8
  Top Layer w0.12: v1(23.726,21.876) 25.074,21.876 25.68,22.483 25.68,23.058 26.07,23.448 26.07,25.995 26.679,26.604 41.871,26.604 v1(42.05,26.425) ; R19.2@32.925,61.475 33.15,61.7 C10.1@34.175,61.7 34.896,61.7 37.121,59.475 v1(37.875,59.475)
  Bottom Layer w0.12: SB64.1@22.825,13.625 22.825,13.883 23.36,14.418 23.36,15.025 23.21,15.175 23.21,21.36 v1(23.726,21.876) ; v1(37.875,59.475) 37.89,59.46 37.89,56.313 39.232,54.971 39.232,54.966 39.916,54.282 39.921,54.282 40.611,53.592 40.611,51.337 42.08,49.868 42.08,35.633 40.67,34.223 40.67,28.355 42.05,26.975 v1(42.05,26.425)
NetB1_3: B1.3 B1.4 C20.2 R28.2 R30.2 | length 14.3
  Top Layer w0.4: B1.4@11.125,50.51 B1.3@20.625,50.51 21.015,50.9 R28.2@22.475,50.9 C20.2@22.475,49.525 R30.2@22.475,48.15
NetB2_1: B2.1 B2.2 C22.2 R31.2 | length 17.3
  Top Layer w0.4: C22.2@22.8,44.275 23.5,44.275 R31.2@23.7,44.075 23.7,44.325 25.385,46.01 v1@25.965,46.01 ; v1(25.95,46.025) v1@25.965,46.01 ; B2.2@27.875,46.01 B2.2@27.635,46.01 v1@25.965,46.01 ; v1(35.485,46.01) B2.1@37.135,46.01
  Bottom Layer w0.4: v1(25.95,46.025) 25.965,46.01 v1(35.485,46.01)
NetC5_2: C5.2 C6.2 D3.2 D4.2 D5.2 U3.1 U3.3 | length 12.3
  Top Layer w0.45: D5.2@45.845,62.5 D4.2@45.845,64.5 ; D3.2@45.845,66.5 D4.2@45.845,64.5 ; U3.3@50.35,62.375 51.15,62.375 51.475,62.7 51.475,62.876 51.5,62.901 51.5,63.726 50.951,64.275 U3.1@50.35,64.275 C6.2@48.725,64.275 C5.2@47.375,64.275 47.15,64.5 D4.2@45.845,64.5
NetC8_2: C8.2 U3.4 | length 1.7
  Top Layer w0.508: U3.4@52.55,62.375 C8.2@54.3,62.375
NetC24_2: C24.2 C27.2 SB13.1 U7.4 | length 6.3
  Top Layer w0.4: v1(15.95,41.125) C27.2@15.95,42 C24.2@15.95,43.35 16.275,43.675 U7.4@16.95,43.675
  Bottom Layer w0.4: v1(15.95,41.125) 15.95,42.875 16.275,43.2 17.05,43.2
NetC49_2: C49.2 C50.2 SB76.2 SB79.1 U13.A2 U13.A3 U14.A3 U14.B2 | length 9.8
  Top Layer w0.12: U14.B2@33.888,4.8 34.138,5.05 U14.A3@34.2,5.05 34.95,5.05 35.4,5.5 C49.2@35.4,5.6 ; U13.A3@33.975,6.25 U13.A2@33.975,6.75 35.275,6.75 v1(35.35,6.675) 35.35,5.65 C49.2@35.4,5.6 ; C50.2@35.4,4.25 C49.2@35.4,5.6
  Bottom Layer w0.12: 34.35,9.8 34.425,9.725 34.425,8 35.35,7.075 v1(35.35,6.675)
NetCN1_4: CN1.4 R2.2 | length 3.2
  Top Layer w0.25: R2.2@33.75,71.3 34.45,71.3 35.545,72.395 CN1.4@35.545,73.31
NetCN2_1: CN2.1 SB1.1 SB2.2 | length 5.4
  Bottom Layer w0.12: SB2.2@8.855,74.93 CN2.1@11.43,74.93 SB1.1@14.105,74.93 13.985,75.05
NetCN2_2: CN2.2 SB3.1 SB4.2 | length 5.3
  Bottom Layer w0.12: SB4.2@8.855,72.39 CN2.2@11.43,72.39 SB3.1@14.105,72.39
NetCN2_3: CN2.3 SB5.1 SB6.2 | length 5.3
  Bottom Layer w0.12: SB6.2@8.855,69.85 CN2.3@11.43,69.85 SB5.1@14.105,69.85
NetCN2_4: CN2.4 SB7.1 SB8.2 | length 5.3
  Bottom Layer w0.12: SB8.2@8.855,67.31 CN2.4@11.43,67.31 SB7.1@14.105,67.31
NetCN3_1: CN3.1 D2.1 R8.1 | length 5.4
  Top Layer w0.4: CN3.1@-2.54,68.58 D2.1@0.835,68.58 0.835,70.115 R8.1@1.205,70.485
NetCN3_2: CN3.2 R11.1 | length 4
  Top Layer w0.4: CN3.2@-2.54,66.04 -1.905,66.675 R11.1@1.205,66.675
NetCN3_4: CN3.4 R14.1 | length 6
  Top Layer w0.4: CN3.4@-2.54,60.96 -0.6,62.9 -0.6,64 0.17,64.77 R14.1@1.205,64.77
NetCN3_5: CN3.5 R17.1 | length 6.2
  Top Layer w0.4: CN3.5@-2.54,58.42 -0.45,60.51 -0.45,61.55 0.865,62.865 R17.1@1.205,62.865
NetCN3_6: CN3.6 R20.1 | length 6.6
  Top Layer w0.4: CN3.6@-2.54,55.88 -0.55,57.87 -0.55,59.205 R20.1@1.205,60.96
NetCN8_1: CN8.1 R35.1 | length 3.1
  Top Layer w0.4: CN8.1@0,35.56 CN8.1@0,35.7
  Top Layer w0.7: CN8.1@0,35.56 0.115,35.675 R35.1@2.875,35.675
NetD1_2: D1.2 R7.1 | length 1.5
  Top Layer w0.3: R7.1@26.035,71.185 26.045,71.175 D1.2@27.505,71.175
NetD2_2: D2.2 R16.1 | length 9.1
  Top Layer w0.127: D2.2@2.975,68.58 2.98,68.575 v1(4.6,68.575) ; v1(4.575,63.525) R16.1@6.925,63.525
  Bottom Layer w0.127: v1(4.575,63.525) 4.575,68.575 v1(4.6,68.575)
NetL1_1: L1.1 U11.A1 U12.3 | length 8.5
  Top Layer w0.12: L1.1@8.304,10.204 8.383,10.125 L1.1@9.1,10.125
  Top Layer w0.2: U11.A1@6.775,11.05 6.805,11.02 6.805,10.983 7.129,10.66 7.965,10.66 8.3,10.325 L1.1@8.3,10.2 ; L1.1@9.1,10.125 9.944,10.125 10.424,10.605 13.41,10.605 13.8,10.215 13.8,10.1 U12.3@13.8,9.55
NetL2_1: L2.1 SB74.1 SB77.2 SB78.2 | length 5.1
  Top Layer w0.12: L2.1@28.925,8.8 L2.1@29.225,9.1
  Top Layer w0.2: L2.1@29.225,9.1 v1(30.15,9.1)
  Bottom Layer w0.2: SB77.2@26.375,9.05 SB78.2@27.775,9.05 27.825,9.1 v1(30.15,9.1)
NetL3_1: L3.1 U13.A1 U14.C3 | length 10.4
  Top Layer w0.15: U14.C3@34.2,4.55 34.325,4.55
  Top Layer w0.2: U13.A1@33.975,7.25 35.625,7.25 36.075,6.8 36.075,3.059 35.98,2.964 35.98,2.605 35.875,2.5 L3.1@35.425,2.5 ; 34.325,4.55 34.625,4.25 34.625,2.725 34.85,2.5 L3.1@35.425,2.5 ; L3.1@35.425,2.2 L3.1@35.425,2.5
NetLD1_2: LD1.2 R10.1 | length 1.4
  Top Layer w0.45: R10.1@50.275,68.175 50.275,69.615 LD1.2@50.28,69.62
NetLD1_3: LD1.3 R9.1 | length 1.4
  Top Layer w0.4: R9.1@48.775,68.175 48.775,69.615 LD1.3@48.78,69.62
NetLD2_1: LD2.1 R21.1 | length 1.8
  Top Layer w0.4: R21.1@47.35,60.325 LD2.1@49.2,60.325
NetLD2_2: LD2.2 U4.3 | length 3.3
  Top Layer w0.4: U4.3@49.9,57.4 49.9,58.35 50.7,59.15 LD2.2@50.7,60.325
NetLD3_1: LD3.1 R29.1 | length 1.2
  Top Layer w0.5: R29.1@37.7,42.5 38.875,42.5 LD3.1@38.9,42.525
NetLD4_1: LD4.1 R34.2 | length 1.2
  Top Layer w0.5: R34.2@37.7,36.25 38.825,36.25 LD4.1@38.9,36.175
NetLD4_2: LD4.2 Q2.3 | length 1.9
  Top Layer w0.5: LD4.2@38.9,37.675 39.7,37.675 Q2.3@40.45,36.925
NetQ1_1: Q1.1 R13.2 R15.2 R18.1 | length 4.6
  Top Layer w0.4: Q1.1@38.625,63.775 40.175,63.775 R15.2@40.2,63.8 ; R18.1@40.2,62.3 R15.2@40.2,63.8 ; R13.2@40.2,65.3 R15.2@40.2,63.8
NetQ1_2: Q1.2 R12.1 | length 1.4
  Top Layer w0.127: R12.1@36.7,65.2 R12.1@36.725,65.175
  Top Layer w0.3: Q1.2@36.725,63.775 R12.1@36.725,65.175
